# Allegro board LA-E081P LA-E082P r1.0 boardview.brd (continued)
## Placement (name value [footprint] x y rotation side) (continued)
PR943  0_0603_5%  [R0603_0OHM]  14.27 21.56 90 top
PR944  442K_0402_1%  [R_0402]  12.29 16.01 0 bottom
PR945  100K_0402_5%  [R_0402]  13.21 17.77 180 bottom
PR946  0_0402_5%  [R0402_0OHM]  28.7 29.88 180 top
PR947  0_0402_5%  [R0402_0OHM]  18.17 8.27 0 top
PR948  16.5K_0402_1%  [R_0402]  20.07 12.39 270 top
PR949  0_0402_5%  [R0402_0OHM]  18.24 12.39 270 top
PR950  0_0402_5%  [R_0402]  28.71 25.55 180 top
PR951  0_0402_5%  [R0402_0OHM]  14.61 11.45 90 top
PR953  100K_0402_1%  [R_0402]  25.85 29.05 180 top
PR960  0_0402_5%  [R0402_0OHM]  12.32 18.57 270 top
PR1201  240K_0402_1%  [R_0402]  67.2 111.31 270 top
PR1202  300K_0402_1%  [R_0402]  4.2 39.23 90 top
PR1203  1.8M_0402_1%  [R_0402]  68.1 109.14 180 top
PR1205  499K_0402_1%  [R_0402]  7.75 51.58 270 top
PR1206  1K_0402_1%  [R_0402]  64.54 109.59 0 bottom
PR1207  499K_0402_1%  [R_0402]  9.39 41.72 0 top
PR1208  102K_0402_1%  [R_0402]  66.42 112.18 270 bottom
PR1209  100K_0402_5%  [R_0402]  3.22 40.12 270 top
PR1210  1M_0402_5%  [R_0402]  12.74 37.69 0 top
PR1211  0_0402_5%  [R0402_0OHM]  18.03 37.73 0 top
PR1212  49.9K_0402_1%  [R_0402]  3.64 49.36 180 top
PR1213  49.9K_0402_1%  [R_0402]  10.29 40.66 270 top
PR1214  100K_0402_5%  [R_0402]  18.3 31.83 180 top
PR1215  0_0402_5%  [R0402_0OHM]  23.25 33.93 90 top
PR1216  0_0402_5%  [R0402_0OHM]  17.15 33.63 180 top
PR1217  84.5K_0402_1%  [R_0402]  67.32 112.16 0 bottom
PR1218  0_0402_5%  [R0402_0OHM]  16.46 31.78 90 top
PR1219  23.2K_0402_1%  [R_0402]  68.07 111.27 0 top
PR1220  0_0402_5%  [R0402_0OHM]  15.24 37.54 0 top
PR1221  0_0402_5%  [R0402_0OHM]  21.34 34.44 0 top
PR1222  100K_0402_5%  [R_0402]  16.13 38.5 180 top
PR1223  0_0402_5%  [R0402_0OHM]  14.36 31.11 180 top
PR1224  100K_0402_5%  [R_0402]  22.23 35.32 90 top
PR1225  0_0402_5%  [R0402_0OHM]  22.1 30.88 180 top
PR1226  100K_0402_5%  [R_0402]  23.25 32.02 90 top
PR1227  100K_0402_5%  [R_0402]  16.64 85.11 270 top
PR1228  499K_0402_1%  [R_0402]  13.98 51.45 0 top
PR1229  49.9K_0402_1%  [R_0402]  15.93 52.29 90 top
PR1230  100K_0402_5%  [R_0402]  25.28 31.25 90 top
PR1231  100K_0402_5%  [R_0402]  31.78 33.76 270 top
PR1232  100K_0402_5%  [R_0402]  28.84 37.56 0 top
PR1233  100K_0402_5%  [R_0402]  28 31.26 0 top
PR1234  100K_0402_5%  [R_0402]  25.48 36.89 90 top
PR1235  100K_0402_5%  [R_0402]  25.41 34.18 270 top
PR1236  100K_0402_5%  [R_0402]  18.7 55.83 180 top
PR1237  100K_0402_1%  [R_0402]  69.24 103.04 90 bottom
PR1238  0_0402_5%  [R0402_0OHM]  68.65 105.44 180 top
PR1239  150K_0402_1%  [R_0402]  72.76 105.66 180 bottom
PR1240  100K_0402_1%  [R_0402]  67.54 103 90 top
PR1241  0_0402_5%  [R0402_0OHM]  32.28 36.09 180 top
PR1242  0_0402_5%  [R0402_0OHM]  26.22 31.26 0 top
PR1243  0_0402_5%  [R0402_0OHM]  66.61 103.91 270 top
PR1244  0_0402_5%  [R0402_0OHM]  65.46 108.65 180 bottom
PR1245  0_0402_5%  [R0402_0OHM]  30.87 31.32 180 top
PR1246  100K_0402_1%  [R_0402]  71.84 106.63 0 bottom
PR1247  100K_0402_1%  [R_0402]  68.36 103.95 270 bottom
PR1248  0_0402_5%  [R_0402]  69.92 110.26 0 top
PR1249  10K_0402_5%  [R_0402]  69.98 112.18 180 top
PR1250  0_0402_5%  [R0402_0OHM]  69.94 111.21 0 top
PR1251  300K_0402_1%  [R_0402]  3.17 55.01 0 top
PR1252  100K_0402_5%  [R_0402]  10.96 37.68 0 top
PR1253  100K_0402_5%  [R_0402]  11.05 33.55 0 top
PR1254  0_0402_5%  [R_0402]  18.04 38.63 0 top
PR1255  150K_0402_1%  [R_0402]  13.98 49.68 0 top
PR1257  0_0402_5%  [R0402_0OHM]  24.52 33.27 90 top
PR1258  0_0402_5%  [R_0402]  32.28 35.2 180 top
PR1259  100K_0402_5%  [R_0402]  26.55 38.25 0 top
PR1260  0_0402_5%  [R_0402]  24.52 35.98 270 top
PR1261  0_0402_5%  [R_0402]  25.41 35.07 90 top
PRP1  100_0804_8P4R_5%  [RP_0804_8P4R]  19.45 5.54 90 top
PT1  PAD~D  [TPC12]  71.75 111.45 0 top
PU1  MC74VHC1G08DFT2G_SC70-5  [TC7SH08FU_SSOP5]  65.25 96.09 270 bottom
PU2  AP2204RA-3.3TRG1_SOT89-3  [AP2204RA-3P3TRG1_SOT89-3]  72.27 101.21 90 bottom
PU100  -  [SY8288BRAC_QFN20_3X3]  156.99 111.26 180 top
PU102  -  [SY8288CRAC_QFN20_3X3]  166.14 113.72 0 bottom
PU200  -  [SY8210AQVC_QFN19_4X3]  44.21 49.79 270 bottom
PU301  SY8286RAC_QFN20_3X3  [SY8288RAC_QFN20_3X3]  179.56 93.48 0 bottom
PU401  TPS62134CRGT_QFN16_3X3  [SY8057QDC_QFN16_3X3]  140.48 108.18 90 top
PU402  TPS62134DRGT_QFN16_3X3  [SY8057QDC_QFN16_3X3]  130.08 110.54 90 top
PU501  -  [RT8097ALGE_SOT23-6]  122.1 105.89 0 top
PU503  -  [AP7361C-FGE-7_U-DFN3030-8_3X3]  193.24 4.81 270 top
PU602  ISL95857AHRTZTS27_TQFN40_5X5~D  [ISL62883CHRTZ-T_TQFN40_5X5-S]  70.56 52.66 180 top
PU610  CSD97396Q4M_VSON8_3P5X4P5  [CSD97374CQ4M_SON8_3P5X4P5]  61.89 71.83 270 bottom
PU612  CSD97396Q4M_VSON8_3P5X4P5  [CSD97374CQ4M_SON8_3P5X4P5]  61.86 65.89 270 bottom
PU614  ISL95808HRZ-TS2778_DFN8_2X2~D  [ISL95808HRZ-TS2378_DFN8_2X2-S]  67.09 78.76 0 bottom
PU901  ISL88738HRTZ REV.B-T TQFN 32P PWM  [ISL88738HRTZ-T_TQFN32_4X4]  20.5 15.56 180 top
PU903  MC74VHC1G08DFT2G_SC70-5  [TC7SH08FU_SSOP5]  29.87 27.6 90 top
PU1200  MC74VHC1G08DFT2G_SC70-5  [TC7SH08FU_SSOP5]  18.79 36.64 180 top
PU1201  -  [LM393DGKR_VSSOP8]  66.92 109.73 270 bottom
QC2  -  [DMN65D8LDW-7_SOT363-6]  151.96 65.6 90 top
QE2  -  [DMN65D8LDW-7_SOT363-6]  298.22 61.93 180 top
QE3  LMBT3904WT1G SC70-3  [MMBT3904WT1G_SC70-3]  122.98 58.09 90 top
QE4  LMBT3904WT1G SC70-3  [MMBT3904WT1G_SC70-3]  284.1 72.92 90 top
QE5  LMBT3904WT1G SC70-3  [MMBT3904WT1G_SC70-3]  239.15 8.97 180 bottom
QE6  LMBT3904WT1G SC70-3  [MMBT3904WT1G_SC70-3]  78.75 48.66 180 top
QE7  LMBT3904WT1G SC70-3  [MMBT3904WT1G_SC70-3]  113.04 8.27 180 bottom
QE11  -  [L2N7002WT1G_SC-70-3]  280.04 70.44 180 top
QE12  -  [L2N7002WT1G_SC-70-3]  287.15 72.98 180 top
QE13  -  [DMN65D8LDW-7_SOT363-6]  293.39 90.63 180 top
QL1  -  [DMN65D8LDW-7_SOT363-6]  283.15 97.67 90 top
QL2  -  [DMN65D8LDW-7_SOT363-6]  278.2 98.97 270 top
QN1  -  [DMN65D8LDW-7_SOT363-6]  281.18 38.5 90 top
QN4  DMN65D8LDW-7_SOT363-6  [DMN66D0LDW-7_SOT363-6]  208.73 35.72 270 top
QN5  DMN65D8LDW-7_SOT363-6  [DMN66D0LDW-7_SOT363-6]  223.84 34.17 90 top
QR1  -  [L2N7002WT1G_SC-70-3]  32.96 52.98 180 top
QT1  -  [DMN66D0LDW-7_SOT363-6]  37.39 81.05 0 top
QV1  -  [AO6405_TSOP6]  109.79 80.95 180 bottom
QV2  -  [L2N7002WT1G_SC-70-3]  102.17 81.99 90 bottom
QV3  -  [DMN65D8LDW-7_SOT363-6]  115 110.97 270 bottom
QV4  -  [L2N7002WT1G_SC-70-3]  112.15 102.33 0 top
QV5  -  [L2N7002WT1G_SC-70-3]  116.14 108.32 180 top
QV7  -  [L2N7002WT1G_SC-70-3]  120.91 83.84 180 bottom
QV8  -  [LP2301ALT1G_SOT23-3]  124.72 88.66 90 bottom
QZ1  -  [LP2301ALT1G_SOT23-3]  112.91 83.8 0 bottom
QZ2  -  [DMN65D8LDW-7_SOT363-6]  267.33 64.85 0 top
QZ3  DDTA114EUA-7-F_SOT323-3  [DDTA144VCA-7-F_SOT23-3]  269.58 73.68 180 top
QZ7  -  [DMN65D8LDW-7_SOT363-6]  315.71 97.49 0 bottom
QZ8  -  [L2N7002WT1G_SC-70-3]  292.49 67.02 90 top
QZ9  -  [LP2301ALT1G_SOT23-3]  173.96 43.39 90 top
R274  0_0603_5%  [R0603_0OHM]  20.96 44.79 90 top
RA3  0_0603_5%  [R0603_0OHM]  302.65 42.5 90 top
RA5  2.2K_0402_5%  [R_0402]  310.22 38.12 180 bottom
RA6  2.2K_0402_5%  [R_0402]  310.22 35.58 180 bottom
RA7  16.2_0402_1%  [R_0402]  307.09 38.32 270 top
RA8  16.2_0402_1%  [R_0402]  307.09 35.63 90 top
RA9  33_0402_5%  [R_0402]  290.82 36.15 0 top
RA12  1K_0402_5%  [R_0402]  300.47 28.09 0 top
RA13  1K_0402_5%  [R_0402]  295.79 29.05 270 top
RA14  22_0402_5%  [R_0402]  292.6 37.99 0 top
RA17  33_0402_5%  [R_0402]  293.51 37.1 180 top
RA18  10K_0402_5%  [R_0402]  296.02 40.92 180 top
RA35  0_0402_5%  [R0402_0OHM]  308.42 42.87 90 top
RA36  0_0402_5%  [R0402_0OHM]  307.54 42.87 90 top
RA37  0_0402_5%  [R0402_0OHM]  294.47 29.04 180 top
RA44  100K_0402_5%  [R_0402]  306.89 32.15 0 top
RA45  10K_0402_5%  [R_0402]  297.69 29.05 270 top
RA48  0_0402_5%  [R0402_0OHM]  296.11 44.04 270 top
RA50  0_0402_5%  [R_0402]  296.87 41.34 90 top
RA51  10K_0402_5%  [R_0402]  298.71 29.05 270 top
RA52  100K_0402_5%  [R_0402]  292.36 38.88 0 top
RA53  0_0402_5%  [R_0402]  303.79 29.11 270 top
RA54  0_0402_5%  [R0402_0OHM]  302.9 29.11 270 top
RA57  4.7K_0402_5%  [R_0402]  305.37 36.52 45 top
RA58  4.7K_0402_5%  [R_0402]  305.37 35.25 45 top
RA59  100K_0402_1%  [R_0402]  293.62 31.9 0 top
RA60  200K_0402_1%  [R_0402]  294.45 30.83 270 top
RA61  100K_0402_1%  [R_0402]  296.22 30.8 0 top
RC1  100K_0402_5%  [R_0402]  132.29 62.5 180 top
RC2  24.9_0402_1%  [R_0402]  108.09 67.58 180 top
RC3  100_0402_1%  [R_0402]  128.91 78.5 0 top
RC4  200_0402_1%  [R_0402]  145.6 52.85 0 bottom
RC5  121_0402_1%  [R_0402]  130.94 42.83 270 top
RC6  80.6_0402_1%  [R_0402]  128.91 42.83 270 top
RC7  100_0402_1%  [R_0402]  129.93 42.83 270 top
RC10  1K_0402_1%  [R_0402]  166.29 49.81 270 top
RC11  1K_0402_1%  [R_0402]  161.46 49.81 270 top
RC12  1K_0402_5%  [R_0402]  148.67 65.1 180 top
RC13  10K_0402_5%  [R_0402]  133.74 37.74 270 top
RC14  1K_0402_5%  [R_0402]  153.34 67.01 0 top
RC15  1K_0402_5%  [R_0402]  145.67 62.5 0 bottom
RC16  15_0402_5%  [R_0402]  138.82 41.92 90 top
RC17  1K_0402_5%  [R_0402]  145.67 64.66 0 bottom
RC19  499_0402_1%  [R_0402]  150.12 59.33 0 bottom
RC20  499_0402_1%  [R_0402]  149.23 61.49 180 bottom
RC21  8.2K_0402_1%  [R_0402]  137.55 39.77 270 top
RC22  22_0402_5%  [R_0402]  142.5 36.72 270 top
RC23  2.2K_0402_5%  [R_0402]  144.45 63.96 0 top
RC25  4.7K_0402_5%  [R_0402]  145.67 61.36 0 bottom
RC27  8.2K_0402_5%  [R_0402]  138.44 39.77 270 top
RC28  33_0402_5%  [R_0402]  151.34 54.69 180 bottom
RC29  33_0402_5%  [R_0402]  152.02 64.41 270 bottom
RC30  1K_0402_5%  [R_0402]  162.44 58.17 90 bottom
RC31  1K_0402_5%  [R_0402]  156.6 61.12 270 top
RC32  0_0402_5%  [R_0402]  167.3 49.81 270 bottom
RC33  0_0402_5%  [R0402_0OHM]  166.29 49.81 270 bottom
RC34  0_0402_5%  [R0402_0OHM]  165.33 49.8 270 bottom
RC35  0_0402_5%  [R0402_0OHM]  163.81 49.8 270 bottom
RC36  0_0402_5%  [R0402_0OHM]  162.48 49.81 270 bottom
RC37  0_0402_5%  [R0402_0OHM]  162.69 66.36 90 bottom
RC38  0_0402_5%  [R0402_0OHM]  161.46 49.81 270 bottom
RC39  33_0402_5%  [R_0402]  162.69 63.82 90 bottom
RC40  0_0402_5%  [R0402_0OHM]  160.44 49.81 270 bottom
RC41  0_0402_5%  [R0402_0OHM]  159.43 48.9 90 bottom
RC42  0_0402_5%  [R_0402]  160.66 61.37 270 bottom
RC43  33_0402_5%  [R_0402]  162.44 57.12 270 bottom
RC44  113_0402_1%  [R_0402]  130.49 58.27 180 top
RC45  100_0402_1%  [R_0402]  132.33 67.87 0 top
RC46  1M_0402_1%  [R_0402]  117.39 78.42 180 bottom
RC47  10K_0402_5%  [R_0402]  146.56 36.72 270 top
RC48  1K_0402_5%  [R_0402]  133.74 39.78 270 top
RC50  10K_0402_5%  [R_0402]  144.79 36.72 270 top
RC51  10K_0402_5%  [R_0402]  145.67 33.68 270 top
RC52  2.7K_0402_1%  [R_0402]  124.66 61.47 90 top
RC54  10M_0402_5%  [R_0402]  151.52 42.18 0 bottom
RC56  20K_0402_5%  [R_0402]  135.77 39.78 270 top
RC57  20K_0402_5%  [R_0402]  154.63 52.36 270 bottom
RC59  10K_0402_5%  [R_0402]  149.36 36.73 270 top
RC60  0_0402_5%  [R_0402]  157.55 50.45 270 bottom
RC62  0_0402_5%  [R0402_0OHM]  161.02 52.05 90 bottom
RC65  100K_0402_5%  [R_0402]  155.78 50.37 180 bottom
RC67  1K_0402_5%  [R_0402]  132.21 36.34 270 top
RC68  10K_0402_5%  [R_0402]  135.13 30.76 270 top
RC69  1M_0402_5%  [R_0402]  135.77 36.98 90 top
RC71  1K_0402_5%  [R_0402]  97.67 79 90 bottom
RC72  8.2K_0402_5%  [R_0402]  150.75 33.67 270 top
RC73  10K_0402_5%  [R_0402]  151.77 33.67 270 top
RC74  10K_0402_5%  [R_0402]  143.77 36.72 270 top
RC75  10K_0402_5%  [R_0402]  132.85 39.77 270 top
RC77  1K_0402_5%  [R_0402]  90.24 81.16 270 bottom
RC78  60.4_0402_1%  [R_0402]  97.57 77.12 270 bottom
RC79  49.9_0402_1%  [R_0402]  101.61 75.46 90 bottom
RC80  1K_0402_5%  [R_0402]  100.72 79 90 bottom
RC81  51_0402_5%  [R_0402]  103.76 79 90 bottom
RC82  100_0402_5%  [R_0402]  105.8 79 90 bottom
RC83  1K_0402_5%  [R_0402]  93.66 80.24 90 bottom
RC84  499_0402_1%  [R_0402]  96.65 79.91 270 bottom
RC86  51_0402_5%  [R_0402]  104.91 75.46 90 bottom
RC87  1K_0402_5%  [R_0402]  101.73 79 90 bottom
RC88  49.9_0402_1%  [R_0402]  132.85 42.83 270 top
RC89  49.9_0402_1%  [R_0402]  131.96 42.83 270 top
RC90  49.9_0402_1%  [R_0402]  90.86 67.42 180 bottom
RC91  49.9_0402_1%  [R_0402]  90.86 66.41 180 bottom
RC92  33_0402_5%  [R_0402]  128.91 35.44 90 top
RC93  33_0402_5%  [R_0402]  127.02 36.4 180 top
RC94  33_0402_5%  [R_0402]  128.94 38.4 90 top
RC95  33_0402_5%  [R_0402]  128.02 34.61 90 top
RC96  200_0402_1%  [R_0402]  150.12 59.45 90 top
RC109  1K_0402_5%  [R_0402]  88.91 80.38 90 bottom
RC110  10K_0402_1%  [R_0402]  95.51 75.46 180 bottom
RC112  10K_0402_1%  [R_0402]  92.27 80.24 90 bottom
RC113  10K_0402_1%  [R_0402]  95.51 76.47 180 bottom
RC114  49.9_0402_1%  [R_0402]  103.21 67.84 180 top
RC115  1.5K_0402_5%  [R_0402]  130.82 86.25 180 top
RC120  100K_0402_5%  [R_0402]  98.68 79 90 bottom
RC121  0_0402_5%  [R_0402]  77.09 38.36 90 top
RC122  0_0402_5%  [R_0402]  76.08 38.36 90 top
RC123  1K_0402_5%  [R_0402]  67.95 39.27 270 top
RC124  1K_0402_5%  [R_0402]  68.97 39.27 270 top
RC126  1K_0402_5%  [R_0402]  73.54 38.36 90 top
RC128  0_0402_5%  [R_0402]  61.35 41.56 270 top
RC129  0_0402_5%  [R_0402]  62.36 41.56 270 top
RC130  51_0402_5%  [R_0402]  102.75 79 90 bottom
RC131  51_0402_5%  [R_0402]  51.19 29.3 270 top
RC132  150_0402_5%  [R_0402]  63.38 38.36 90 top
RC133  1.5K_0402_5%  [R_0402]  60.33 41.56 270 top
RC134  51_0402_5%  [R_0402]  51.69 35.82 90 top
RC135  100_0402_5%  [R_0402]  53.73 35.82 90 top
RC136  51_0402_5%  [R_0402]  54.23 29.3 270 top
RC137  3K_0402_5%  [R_0402]  62.87 27.59 270 top
RC138  51_0402_5%  [R_0402]  75.06 38.36 90 top
RC139  51_0402_5%  [R_0402]  61.35 38.36 90 top
RC140  100_0402_1%  [R_0402]  113.29 76.74 90 bottom
RC141  100_0402_1%  [R_0402]  114.16 76.74 90 bottom
RC143  0_0603_5%  [R0603_0OHM]  123.69 65.16 180 top
RC152  56_0402_1%  [R_0402]  99.7 76.71 90 bottom
RC153  220_0402_5%  [R_0402]  98.81 75.46 0 bottom
RC157  100_0402_1%  [R_0402]  98.68 76.71 90 bottom
RC161  100_0402_1%  [R_0402]  90.88 64.47 180 bottom
RC163  100_0402_1%  [R_0402]  90.86 65.44 180 bottom
RC165  100_0402_1%  [R_0402]  122.51 53.8 180 top
RC166  100_0402_1%  [R_0402]  121.16 80.39 90 top
RC167  100_0402_1%  [R_0402]  123.58 53.85 90 top
RC168  100_0402_1%  [R_0402]  122.43 81.3 270 top
RC169  0_0603_5%  [R0603_0OHM]  148.53 72.15 180 top
RC170  0_0402_5%  [R0402_0OHM]  125.46 81.16 270 top
RC171  0_0402_5%  [R0402_0OHM]  136.53 85.57 270 top
RC173  0_0402_5%  [R0402_0OHM]  126.37 80.41 180 bottom
RC175  2.2K_0402_5%  [R_0402]  140.09 88.97 90 top
RC176  2.2K_0402_5%  [R_0402]  121.35 83.91 90 top
RC177  2.2K_0402_5%  [R_0402]  120.34 83.91 90 top
RC178  2.2K_0402_5%  [R_0402]  139.07 88.97 90 top
RC183  8.2K_0402_5%  [R_0402]  148.34 36.72 270 top
RC184  8.2K_0402_5%  [R_0402]  149.74 39.85 270 top
RC186  4.7K_0402_5%  [R_0402]  148.72 33.68 270 top
RC187  4.7K_0402_5%  [R_0402]  130.94 39.77 270 top
RC189  10K_0402_5%  [R_0402]  147.71 33.68 270 top
RC190  10K_0402_5%  [R_0402]  141.86 38.89 270 top
RC211  0_0402_5%  [R_0402]  154.69 56.03 270 top
RC212  0_0402_5%  [R0402_0OHM]  155.58 56.03 270 top
RC214  0_0402_5%  [R0402_0OHM]  137.8 41.91 90 top
RC215  0_0402_5%  [R_0402]  131.83 38.88 90 top
RC216  0_0603_1%  [R0603_0OHM]  65.92 26.18 90 top
RC217  0_0402_5%  [R_0402]  63.38 41.56 270 top
RC218  150_0402_5%  [R_0402]  64.39 41.56 270 top
RC219  10K_0402_5%  [R_0402]  65.41 41.56 270 top
RC220  100K_0402_1%  [R_0402]  131.07 36.35 270 top
RC221  0_0402_5%  [R0402_0OHM]  278.77 92.02 90 bottom
RC222  1K_0402_5%  [R_0402]  279.79 92.02 90 bottom
RC223  1K_0402_5%  [R_0402]  129.82 38.4 90 top
RC224  1K_0402_5%  [R_0402]  148.16 88.47 180 bottom
RC225  8.2K_0402_5%  [R_0402]  151.39 90.81 90 bottom
RC227  8.2K_0402_5%  [R_0402]  151.39 89.44 270 bottom
RC228  0_0402_5%  [R0402_0OHM]  52.2 29.3 270 top
RC229  0_0402_5%  [R0402_0OHM]  52.71 35.82 90 top
RC230  0_0402_5%  [R0402_0OHM]  104.78 79.91 270 bottom
RC231  0_0402_5%  [R0402_0OHM]  111.89 54.12 180 top
RC234  0_0402_5%  [R_0402]  151.21 56.85 180 bottom
RC235  0_0402_5%  [R0402_0OHM]  151.21 56.85 180 top
RC237  10K_0402_5%  [R_0402]  150.35 54.88 0 top
RC239  0_0402_5%  [R_0402]  71.25 39.27 270 top
RC240  0_0402_5%  [R_0402]  70.24 39.27 270 top
RC241  1.5K_0402_5%  [R_0402]  64.9 38.36 90 top
RC243  10K_0402_5%  [R_0402]  133.36 31.26 270 top
RC244  0_0402_5%  [R0402_0OHM]  160.13 52.05 90 bottom
RC267  10K_0402_5%  [R_0402]  147.71 39.85 270 top
RC268  10K_0402_5%  [R_0402]  148.72 39.85 270 top
RC272  10K_0402_5%  [R_0402]  137.93 81.17 180 bottom
RC278  10K_0402_5%  [R_0402]  151.64 39.77 270 top
RC279  10K_0402_5%  [R_0402]  144.53 58.57 0 top
RC282  100K_0402_5%  [R_0402]  152.79 54.88 0 top
RC283  10K_0402_5%  [R_0402]  145.6 57.86 0 bottom
RC287  100K_0402_5%  [R_0402]  145.6 58.88 0 bottom
RC288  10K_0402_5%  [R_0402]  147.2 75.84 0 top
RC290  0_0402_5%  [R0402_0OHM]  150.2 88.47 180 bottom
RC291  10K_0402_5%  [R_0402]  146.31 89.79 90 bottom
RC292  10K_0402_5%  [R_0402]  133.61 86.51 270 top
RC295  33_0402_5%  [R_0402]  117.44 79.32 0 bottom
RC296  0_0402_5%  [R0402_0OHM]  150.63 42.18 90 bottom
RC297  0_0402_5%  [R_0402]  112.38 76.74 90 bottom
RC298  0_0402_5%  [R_0402]  111.49 76.74 90 bottom
RC299  0_0603_5%  [R0603_0OHM]  133.74 82.06 270 bottom
RC300  0_0402_5%  [R0402_0OHM]  138.51 85.62 180 top
RC301  0_0402_5%  [R0402_0OHM]  146.49 66.31 180 bottom
RC302  0_0402_5%  [R0402_0OHM]  132.59 86.25 180 top
RC303  0_0402_5%  [R0402_0OHM]  128.26 80.9 270 top
RC304  0_0402_5%  [R0402_0OHM]  145.42 59.58 180 top
RC305  0_0402_5%  [R0402_0OHM]  130.87 56.36 180 top
RC306  0_0402_5%  [R0402_0OHM]  151.25 57.73 180 top
RC307  0_0402_5%  [R0402_0OHM]  145.42 57.55 180 top
RC308  0_0402_5%  [R0402_0OHM]  145.42 60.47 180 top
RC309  0_0603_5%  [R0603_0OHM]  120.02 79.9 90 top
RC310  0_0603_5%  [R0603_0OHM]  148.6 73.42 180 top
RC311  10K_0402_5%  [R_0402]  133.99 42.83 270 top
RC313  0_0402_5%  [R_0402]  145.29 69.11 180 top
RC316  1K_0402_5%  [R_0402]  155.58 61.12 270 top
RC317  150K_0402_5%  [R_0402]  148.98 57.55 180 bottom
RC318  2.2K_0402_5%  [R_0402]  148.16 67.01 180 top
RC319  2.2K_0402_5%  [R_0402]  153.34 65.99 0 top
RC323  10K_0402_5%  [R_0402]  143.64 33.68 270 top
RC324  59_0402_1%  [R_0402]  113.52 67.24 270 top
RC325  0_0402_5%  [R0402_0OHM]  156.66 50.45 270 bottom
RC328  0_0402_5%  [R0402_0OHM]  102.49 78 180 bottom
RC330  49.9K_0402_1%  [R_0402]  145.6 54.82 0 bottom
RC331  49.9K_0402_1%  [R_0402]  145.6 55.83 0 bottom
RC337  0_0402_5%  [R0402_0OHM]  151.77 36.8 270 top
RC338  1K_0402_5%  [R_0402]  150.75 39.85 270 top
RC344  10K_0402_5%  [R_0402]  136.15 30.76 270 top
RC345  100K_0402_5%  [R_0402]  144.4 68.22 0 top
RC346  10K_0402_5%  [R_0402]  151.52 75.33 0 bottom
RC347  499_0402_1%  [R_0402]  150.12 60.22 0 bottom
RC348  499_0402_1%  [R_0402]  150.12 61.49 0 bottom
RC349  100_0402_1%  [R_0402]  140.09 39.77 270 top
RC362  1K_0402_5%  [R_0402]  147.96 54.76 0 top
RC363  1K_0402_5%  [R_0402]  147.96 55.64 0 top
RC366  15_0402_5%  [R_0402]  138.69 36.72 270 top
RC367  15_0402_5%  [R_0402]  139.58 36.72 270 top
RC368  15_0402_5%  [R_0402]  136.66 39.77 270 top
RC369  15_0402_5%  [R_0402]  140.59 36.72 270 top
RC370  10K_0402_5%  [R_0402]  153.42 39.77 270 top
RC371  10K_0402_5%  [R_0402]  145.57 67.33 0 bottom
RC372  10K_0402_5%  [R_0402]  148.09 67.84 0 bottom
RC373  0_0402_5%  [R0402_0OHM]  146.69 33.68 270 top
RC374  0_0402_5%  [R0402_0OHM]  147.45 36.72 270 top
RC375  0_0402_5%  [R0402_0OHM]  145.67 36.72 270 top
RC376  0_0402_5%  [R0402_0OHM]  150.37 36.73 270 top
RC377  0_0402_5%  [R0402_0OHM]  144.66 33.68 270 top
RC378  0_0402_5%  [R0402_0OHM]  140.98 38.88 270 top
RC387  10K_0402_5%  [R_0402]  149.74 33.68 270 top
RC400  10K_0402_5%  [R_0402]  145.57 68.22 0 bottom
RC401  10K_0402_5%  [R_0402]  148.09 68.73 0 bottom
RC402  49.9K_0402_1%  [R_0402]  145.6 53.8 0 bottom
RC403  49.9K_0402_1%  [R_0402]  145.6 56.85 0 bottom
RC404  10K_0402_5%  [R_0402]  144.4 67.33 0 top
RC405  100K_0402_5%  [R_0402]  145.67 59.84 0 bottom
RC407  33_0402_5%  [R_0402]  156.66 61.37 270 bottom
RC408  33_0402_5%  [R_0402]  157.61 61.37 270 bottom
RC409  33_0402_5%  [R_0402]  158.63 61.37 270 bottom
RC410  33_0402_5%  [R_0402]  159.64 61.37 270 bottom
RC411  10K_0402_5%  [R_0402]  125.16 36.42 270 top
RC413  10K_0402_5%  [R_0402]  141.1 88.97 90 top
RC414  10K_0402_5%  [R_0402]  140.85 42.83 270 top
RC417  33_0402_5%  [R_0402]  115.66 79.33 0 bottom
RD4  0_0402_5%  [R_0402]  103.64 3.05 90 top
RD5  0_0402_5%  [R0402_0OHM]  102.62 3.97 270 top
RD6  0_0402_5%  [R_0402]  104.65 3.05 90 top
RD7  0_0402_5%  [R0402_0OHM]  105.67 3.97 270 top
RD8  0_0402_5%  [R_0402]  88.52 2.29 90 top
RD9  0_0402_5%  [R0402_0OHM]  88.52 4.32 90 top
RD10  0_0603_5%  [R0603_0OHM]  106.13 7.56 180 top
RD11  470_0402_1%  [R_0402]  64.9 4.22 270 top
RD12  0_0402_5%  [R0402_0OHM]  65.92 4.22 270 top
RD14  1K_0402_5%  [R_0402]  73.03 4.32 90 top
RD15  1K_0402_1%  [R_0402]  86.7 5.29 180 top
RD16  1K_0402_1%  [R_0402]  85.78 4.27 0 top
RD17  2_0402_1%  [R_0402]  83.95 5.24 270 top
RD18  24.9_0402_1%  [R_0402]  85.78 3.25 0 top
RD19  100K_0402_5%  [R_0402]  65.66 18.7 270 top
RD20  0_0402_5%  [R_0402]  186.06 2.29 90 top
RD21  0_0402_5%  [R0402_0OHM]  187.08 3.2 270 top
RD22  0_0402_5%  [R0402_0OHM]  189.11 2.29 90 top
RD23  0_0402_5%  [R_0402]  188.09 3.2 270 top
RD24  0_0402_5%  [R_0402]  169.71 3.5 180 top
RD25  0_0402_5%  [R0402_0OHM]  168.8 2.49 0 top
RD26  0_0603_5%  [R0603_0OHM]  187.84 13.6 270 top
RD27  1K_0402_5%  [R_0402]  141.46 2.49 180 top
RD28  1K_0402_1%  [R_0402]  171.48 5.31 270 top
RD29  1K_0402_1%  [R_0402]  170.46 4.4 90 top
RD30  2_0402_1%  [R_0402]  171.2 3.2 270 top
RD31  24.9_0402_1%  [R_0402]  173.23 3.2 270 top
RE5  10K_0402_5%  [R_0402]  299.22 83.93 90 top
RE6  10K_0402_5%  [R_0402]  41.52 81.04 0 bottom
RE8  100K_0402_5%  [R_0402]  304.81 83.84 90 top
RE10  100K_0402_5%  [R_0402]  307.4 70.08 0 top
RE11  100K_0402_5%  [R_0402]  296.49 69.38 270 top
RE12  100K_0402_5%  [R_0402]  308.11 65.93 270 top
RE13  10K_0402_5%  [R_0402]  41.46 74.95 0 bottom
RE14  10K_0402_5%  [R_0402]  42.37 75.96 180 bottom
RE15  10K_0402_5%  [R_0402]  41.46 78 0 bottom
RE16  10K_0402_5%  [R_0402]  42.37 76.98 180 bottom
RE17  10K_0402_5%  [R_0402]  41.46 79.01 0 bottom
RE18  10K_0402_5%  [R_0402]  42.44 80.03 180 bottom
RE20  100K_0402_5%  [R_0402]  298.28 69.47 270 top
RE21  10K_0402_5%  [R_0402]  299.09 64.46 90 top
RE25  100K_0402_5%  [R_0402]  307.46 85.04 0 top
RE26  10_0402_5%  [R_0402]  308.52 86.86 270 top
RE30  0_0402_5%  [R0402_0OHM]  274.15 78.44 180 bottom
RE31  100K_0402_5%  [R_0402]  286.9 69.92 90 top
RE32  0_0402_5%  [R0402_0OHM]  290.05 77.95 180 top
RE33  1K_0402_5%  [R_0402]  285.88 70.83 270 top
RE34  0_0402_5%  [R0402_0OHM]  284.87 79.58 180 top
RE35  10K_0402_5%  [R_0402]  306.58 84.14 90 top
RE37  2.2K_0402_5%  [R_0402]  307.36 71.85 0 top
RE38  10K_0402_5%  [R_0402]  305.69 84.14 90 top
RE43  2.2K_0402_5%  [R_0402]  307.4 70.97 0 top
RE48  10K_0402_5%  [R_0402]  270.39 41.5 270 bottom
RE51  10K_0402_5%  [R_0402]  266.96 41.29 40 top
RE55  100K_0402_5%  [R_0402]  293.79 69.67 270 top
RE56  10K_0402_5%  [R_0402]  302.83 68.78 270 top
RE57  1K_0402_5%  [R_0402]  295.58 69.41 270 top
RE58  100K_0402_5%  [R_0402]  294.69 69.67 270 top
RE59  0_0402_5%  [R0402_0OHM]  305.65 87.43 270 top
RE60  43_0402_5%  [R_0402]  302.71 83.8 90 top
RE63  100K_0402_5%  [R_0402]  300.87 87.14 90 top
RE64  300_0402_5%  [R_0402]  304.82 68 270 top
RE65  100_0402_1%  [R_0402]  300.17 86 180 top
RE67  10K_0402_5%  [R_0402]  297.06 62.93 90 top
RE68  100K_0402_5%  [R_0402]  297.64 58.95 180 top
RE69  8.2K_0402_5%  [R_0402]  284.41 74.19 0 top
RE70  2.2K_0402_5%  [R_0402]  279.58 73.68 0 top
RE71  49.9_0402_1%  [R_0402]  273.23 79.46 0 bottom
RE72  10K_0402_5%  [R_0402]  273.23 77.42 0 bottom
RE73  10K_0402_5%  [R_0402]  273.23 73.36 0 bottom
RE74  10K_0402_5%  [R_0402]  273.23 72.34 0 bottom
RE75  100K_0402_5%  [R_0402]  273.23 75.39 0 bottom
RE77  1.69K_0402_1%  [R_0402]  293.32 82.57 180 top
RE79  4.3K_0402_5%  [R_0402]  303.79 83.84 90 top
RE83  100K_0402_5%  [R_0402]  302.65 87.14 90 top
RE84  100K_0402_5%  [R_0402]  300.74 92.78 90 top
RE85  100K_0402_5%  [R_0402]  299.73 92.78 90 top
RE86  10K_0402_5%  [R_0402]  274.15 76.41 180 bottom
RE90  0_0402_5%  [R0402_0OHM]  280.5 74.69 180 top
RE91  100K_0402_5%  [R_0402]  301.76 87.14 90 top
RE92  100K_0402_5%  [R_0402]  289.36 68.6 0 top
RE93  100K_0201_5%  [R_0201]  287.7 75.84 180 top
RE94  75_0402_5%  [R_0402]  287.2 71.77 0 top
RE95  100K_0402_5%  [R_0402]  313.62 78.25 0 top
RE98  4.7K_0402_5%  [R_0402]  314.33 67.07 180 top
RE274  0_0402_5%  [R_0402]  308.44 68.31 180 top
RE275  0_0402_5%  [R0402_0OHM]  307.51 67.42 0 top
RE280  0_0402_5%  [R_0402]  305.64 96.03 180 top
RE288  100_0402_5%  [R_0402]  301.12 83.83 90 top
RE290  0_0402_5%  [R0402_0OHM]  293.26 73.12 270 top
RE292  0_0402_5%  [R_0402]  303.61 96.03 180 top
RE300  130K_0402_5%  [R_0402]  300.61 89.88 270 top
RE301  10K_0402_5%  [R_0402]  293.25 83.46 180 top
RE302  2.2K_0402_5%  [R_0402]  289.84 74.36 0 top
RE303  2.2K_0402_5%  [R_0402]  289.84 73.47 0 top
RE304  0_0402_5%  [R_0402]  308.49 93.54 90 top
RE306  0_0402_5%  [R_0402]  273.23 74.38 0 bottom
RE308  0_0402_5%  [R_0402]  306.66 87.43 270 top
RE312  300_0402_5%  [R_0402]  310.2 68.9 270 top
RE313  10K_0402_5%  [R_0402]  311.11 68.91 270 top
RE314  100_0402_1%  [R_0402]  299.94 67.57 0 top
RE318  0_0402_5%  [R0402_0OHM]  296.6 64.87 0 top
RE324  100K_0402_5%  [R_0402]  292.13 68.73 180 top
RE337  0_0402_5%  [R_0402]  306.22 67.13 90 top
RE338  0_0402_5%  [R_0402]  308.69 77.36 180 top
RE339  0_0402_5%  [R_0402]  308.42 72.76 180 top
RE340  10K_0402_5%  [R_0402]  268.09 75.77 0 bottom
RE341  0_0402_5%  [R_0402]  308.3 69.2 180 top
RE342  10K_0402_5%  [R_0402]  302.18 66.99 0 top
RE343  240K_0402_5%  [R_0402]  298.01 66.3 90 top
RE348  10K_0402_5%  [R_0402]  279.58 76.73 0 top
RE349  43K_0402_1%  [R_0402]  308.43 73.64 180 top
RE350  33_0402_5%  [R_0402]  287.74 78.38 180 top
RE360  0_0402_5%  [R0402_0OHM]  313.62 75.46 0 top
RE361  49.9K_0402_1%  [R_0402]  297.05 66.55 180 top
RE362  100K_0402_5%  [R_0402]  297.05 67.57 180 top
RE363  0_0402_5%  [R_0402]  301.97 68.82 270 top
RE364  0_0402_5%  [R0402_0OHM]  307.51 74.51 0 top
RE365  100K_0402_5%  [R_0402]  297.45 83.77 90 top
RE366  24.9_0402_1%  [R_0402]  313.62 77.23 0 top
RE367  45.3_0402_1%  [R_0402]  317.89 73.12 270 top
RE368  24.9_0402_1%  [R_0402]  314.13 74.06 0 top
RE369  45.3_0402_1%  [R_0402]  311.46 65.55 0 top
RE370  24.9_0402_1%  [R_0402]  313.62 76.35 0 top
RE371  45.3_0402_1%  [R_0402]  311.46 64.66 0 top
RE372  24.9_0402_1%  [R_0402]  307.6 76.34 0 top
RE373  45.3_0402_1%  [R_0402]  317 73.12 270 top
RE374  24.9_0402_1%  [R_0402]  307.73 79.52 0 top
RE375  0_0402_5%  [R_0402]  268.17 66.81 90 bottom
RE376  1K_0402_5%  [R_0402]  310.27 64.66 90 top
RE377  1K_0402_5%  [R_0402]  315.98 73.12 270 top
RE505  100K_0402_5%  [R_0402]  269.49 91.02 90 top
RE507  100K_0402_5%  [R_0402]  290.75 75.33 180 top
RE508  100K_0402_5%  [R_0402]  287.33 68.6 0 top
RE512  100K_0402_5%  [R_0402]  309.5 70.88 0 top
RE513  100K_0402_5%  [R_0402]  304.17 70.01 270 bottom
RE514  0_0402_5%  [R_0402]  286.82 76.6 0 top
RE515  0_0402_5%  [R0402_0OHM]  286.82 77.49 0 top
RE524  2.2K_0402_5%  [R_0402]  310.33 78.07 0 top
RE525  2.2K_0402_5%  [R_0402]  310.33 77.2 0 top
RE526  10K_0402_5%  [R_0402]  299.2 90.06 0 bottom
RE530  1M_0402_5%  [R_0402]  292.7 86.58 90 top
RE532  4.7K_0402_5%  [R_0402]  301.91 90.05 180 bottom
RE536  0_0402_5%  [R_0402]  279.6 77.73 0 top
RE537  10K_0402_5%  [R_0402]  284.87 80.47 180 top
RE539  100_0402_5%  [R_0402]  306.67 91.48 0 top
RI13  10K_0402_5%  [R_0402]  305.69 62.5 180 top
RI14  22.1K_0402_1%  [R_0402]  311.79 61.94 270 top
RI27  0_0402_5%  [R_0402-NPM]  292.49 45.43 270 top
RI28  0_0402_5%  [R_0402-NPM]  291.47 45.43 270 top
RI29  0_0402_5%  [R_0402-NPM]  295.6 47.4 270 top
RI30  0_0402_5%  [R_0402-NPM]  294.71 47.4 270 top
RI34  4.7K_0402_5%  [R_0402]  303.66 61.44 270 top
RI35  0_0402_5%  [R_0402]  296.85 53.61 0 top
RI36  4.99K_0402_1%  [R_0402]  305.06 54.4 90 top
RI37  2K_0402_5%  [R_0402]  306.33 50.68 180 top
RI38  4.7K_0402_5%  [R_0402]  302.65 62.68 90 top
RI39  4.7K_0402_5%  [R_0402]  302.65 60.52 90 top
RI40  4.7K_0402_5%  [R_0402]  300.61 62.68 90 top
RI41  4.7K_0402_5%  [R_0402]  300.61 60.52 90 top
RI42  4.7K_0402_5%  [R_0402]  302.07 52.67 270 top
RI43  4.7K_0402_5%  [R_0402]  302.07 50.45 270 top
RI44  4.7K_0402_5%  [R_0402]  300.23 52.67 270 top
RI45  4.7K_0402_5%  [R_0402]  300.23 50.45 270 top
RI47  0_0402_5%  [R_0402-NPM]  290.45 45.43 270 top
RI48  0_0402_5%  [R_0402-NPM]  289.44 45.43 270 top
RI49  0_0402_5%  [R_0402-NPM]  197.73 24.4 0 bottom
RI50  0_0402_5%  [R_0402-NPM]  197.73 23.39 0 bottom
RI51  4.7K_0402_5%  [R_0402]  299.6 62.68 90 top
RI52  4.7K_0402_5%  [R_0402]  299.6 60.52 90 top
RI53  4.7K_0402_5%  [R_0402]  301.63 62.68 90 top
RI54  4.7K_0402_5%  [R_0402]  301.63 60.52 90 top
RI55  4.7K_0402_5%  [R_0402]  306.67 49.83 270 top
RI56  4.7K_0402_5%  [R_0402]  305.78 49.83 270 top
RI57  4.7K_0402_5%  [R_0402]  301.12 52.67 270 top
RI58  4.7K_0402_5%  [R_0402]  301.12 50.45 270 top
RI79  0_0603_5%  [R_0603]  315.78 68.26 180 top
RI80  0_0603_5%  [R0603_0OHM]  315.78 69.46 180 top
RI81  0_0402_5%  [R0402_0OHM]  304.16 51.95 180 top
RL1  10K_0402_5%  [R_0402]  273.13 84.09 180 top
RL2  10K_0402_5%  [R_0402]  273.13 82.57 180 top
RL3  0_0402_5%  [R0402_0OHM]  283.39 84.98 0 top
RL4  4.7K_0402_5%  [R_0402]  279.38 80.5 270 top
RL5  10K_0402_5%  [R_0402]  280.4 80.49 270 top
RL6  4.7K_0402_5%  [R_0402]  283.09 80.47 270 top
RL7  0_0402_5%  [R0402_0OHM]  282.21 79.57 90 top
RL8  0_0603_5%  [R0603_0OHM]  283.53 81.68 0 top
RL9  10K_0402_5%  [R_0402]  281.31 80.49 270 top
RL11  1M_0402_5%  [R_0402]  285.37 89.35 90 top
RL12  1K_0402_5%  [R_0402]  273.13 85.11 180 top
RL13  3.01K_0402_1%  [R_0402]  283.34 89.35 90 top
RL14  150_0402_5%  [R_0402]  279.21 100.53 90 top
RL15  75_0402_1%  [R_0402]  292.99 101.31 270 top
RL16  75_0402_1%  [R_0402]  295.53 101.31 270 top
RL17  75_0402_1%  [R_0402]  298.84 101.31 270 top
RL18  75_0402_1%  [R_0402]  302.39 101.31 270 top
RL19  150_0402_5%  [R_0402]  280.17 100.53 90 top
RL20  150_0402_5%  [R_0402]  282.38 100.48 0 top
RL29  1M_0402_5%  [R_0402]  281.31 101.44 270 top
RL30  1M_0402_5%  [R_0402]  278.26 101.44 270 top
RL34  0_0402_5%  [R0402_0OHM]  285.32 88.16 180 top
RL70  10K_0402_5%  [R_0402]  142.63 33.68 270 top
RL71  2.2_0603_5%  [R_0603]  283.6 91.78 90 top
RL72  2.2_0603_5%  [R_0603]  282.33 91.78 90 top
RL73  2.2_0603_5%  [R_0603]  281.06 91.78 90 top
RL74  2.2_0603_5%  [R_0603]  279.79 91.78 90 top
RL75  2.2_0603_5%  [R_0603]  278.52 91.78 90 top
RL76  2.2_0603_5%  [R_0603]  277.25 91.78 90 top
RL77  2.2_0603_5%  [R_0603]  275.98 91.78 90 top
RL78  2.2_0603_5%  [R_0603]  274.71 91.78 90 top
RN1  100K_0402_5%  [R_0402]  282.26 40.58 90 bottom
RN2  100K_0402_5%  [R_0402]  277.75 38.04 90 top
RN3  10K_0402_5%  [R_0402]  276.48 36.72 90 bottom
RN4  10K_0402_5%  [R_0402]  276.36 40.14 90 bottom
RN5  10K_0402_5%  [R_0402]  276.36 41.92 90 bottom
RN6  4.7K_0402_5%  [R_0402]  271.96 62.76 0 top
RN7  4.7K_0402_5%  [R_0402]  272.04 62.25 0 bottom
RN8  4.7K_0402_5%  [R_0402]  272.88 63.77 180 top
RN9  4.7K_0402_5%  [R_0402]  272.04 63.14 0 bottom
RN10  4.7K_0402_5%  [R_0402]  280.68 62.38 0 top
RN11  4.7K_0402_5%  [R_0402]  278.14 62.38 0 bottom
RN12  4.7K_0402_5%  [R_0402]  281.56 64.53 180 top
RN13  4.7K_0402_5%  [R_0402]  276.23 63.26 0 bottom
RN14  4.7K_0402_5%  [R_0402]  271.96 64.79 0 top
RN15  7.87K_0402_1%  [R_0402]  272.04 64.03 0 bottom
RN16  4.7K_0402_5%  [R_0402]  281.56 60.98 180 top
RN17  4.7K_0402_5%  [R_0402]  278.14 61.49 0 bottom
RN18  4.7K_0402_5%  [R_0402]  279.41 58.62 90 top
RN19  4.7K_0402_5%  [R_0402]  278.45 59.53 270 top
RN20  4.7K_0402_5%  [R_0402]  281.56 63.65 180 top
RN21  4.7K_0402_5%  [R_0402]  279.02 63.26 180 bottom
RN25  10K_0402_5%  [R_0402]  258.83 42.23 90 top
RN26  10K_0402_5%  [R_0402]  260.86 42.11 90 top
RN27  10K_0402_5%  [R_0402]  268.43 44.47 180 top
RN28  10K_0402_5%  [R_0402]  261.88 42.11 90 top
RN30  4.99K_0402_1%  [R_0402]  263.91 43.02 270 top
RN31  4.99K_0402_1%  [R_0402]  294.25 55.33 0 top
RN37  10K_0402_5%  [R_0402]  294 27.77 0 top
RN38  10K_0402_5%  [R_0402]  259.54 44.47 180 top
RN39  10K_0402_5%  [R_0402]  259.85 43.02 270 top
RN40  10K_0402_5%  [R_0402]  267.52 45.48 0 top
RN41  10K_0402_5%  [R_0402]  262.9 43.02 270 top
RN42  10K_0402_5%  [R_0402]  261.75 51.91 270 top
RN43  10K_0402_5%  [R_0402]  261.75 53.15 90 top
RN44  10K_0402_5%  [R_0402]  265.44 52.04 270 top
RN49  10K_0402_5%  [R_0402]  265.94 42.11 90 top
RN50  10K_0402_5%  [R_0402]  264.55 52.04 270 top
RN51  10K_0402_5%  [R_0402]  268.43 47.52 180 top
RN52  10K_0402_5%  [R_0402]  264.93 43.02 270 top
RN53  10K_0402_5%  [R_0402]  263.66 51.12 90 top
RN54  10K_0402_5%  [R_0402]  267.52 46.5 0 top
RN55  10K_0402_5%  [R_0402]  292.61 52.29 270 bottom
RN56  10K_0402_5%  [R_0402]  295.15 52.34 180 top
RN57  10K_0402_5%  [R_0402]  292.99 59.58 180 bottom
RN58  10K_0402_5%  [R_0402]  295.17 53.29 180 top
RN59  10K_0402_5%  [R_0402]  291.67 51.38 90 bottom
RN60  10K_0402_5%  [R_0402]  294.26 51.45 0 top
RN61  10K_0402_5%  [R_0402]  292.11 60.6 0 bottom
RN62  10K_0402_5%  [R_0402]  294.25 54.31 0 top
RN63  10K_0402_5%  [R_0402]  226.14 35.83 180 top
RN64  10K_0402_5%  [R_0402]  219.64 32.28 0 top
RN65  10K_0402_5%  [R_0402]  209.68 32.39 90 top
RN69  10K_0402_5%  [R_0402]  295.17 57.23 180 top
RN70  10K_0402_5%  [R_0402]  288.27 56.15 180 bottom
RN71  10K_0402_5%  [R_0402]  290.96 57.93 180 bottom
RN72  10K_0402_5%  [R_0402]  294.25 56.28 0 top
RN73  10K_0402_5%  [R_0402]  287.36 55.26 0 bottom
RN74  10K_0402_5%  [R_0402]  289.18 57.93 180 bottom
RN77  0_0402_5%  [R0402_0OHM]  286.28 39.13 180 bottom
RN78  0_0402_5%  [R0402_0OHM]  286.28 38.25 180 bottom
RN81  0_0402_5%  [R0402_0OHM]  283.67 42.44 180 bottom
RN82  0_0402_5%  [R0402_0OHM]  283.67 43.33 180 bottom
RN99  0_0402_5%  [R0402_0OHM]  292.22 27.77 0 top
RN100  0_0402_5%  [R_0402]  267.47 25.51 180 bottom
RN101  0_0402_5%  [R_0402]  264.8 25.51 0 bottom
RN171  100K_0402_5%  [R_0402]  212.67 34.93 90 top
RN174  10K_0402_5%  [R_0402]  266.32 51.12 90 top
RN176  10K_0402_5%  [R_0402]  262.64 54.07 270 top
RN179  10K_0402_5%  [R_0402]  262.64 51 90 top
RN182  0_0402_5%  [R_0402]  209.29 36.85 0 top
RN183  100K_0402_5%  [R_0402]  211.71 34 270 top
RN184  0_0402_5%  [R_0402]  226.14 33.8 180 top
RN185  100K_0402_5%  [R_0402]  225.23 32.78 0 top
RN186  0_0402_5%  [R_0402]  226.14 31.77 180 top
RN187  0_0402_5%  [R_0402]  219.64 35.32 0 top
RN188  100K_0402_5%  [R_0402]  220.55 36.34 180 top
RN189  0_0402_5%  [R_0402]  219.64 34.31 0 top
RN192  0_0402_5%  [R_0402]  211.71 35.84 270 top
RN223  0_0402_5%  [R_0402]  208.73 33.3 270 top
RN224  0_0402_5%  [R_0402]  220.55 33.29 180 top
RN225  0_0402_5%  [R_0402]  225.23 34.82 0 top
RPC1  33_0804_8P4R_5%  [RP_0804_8P4R]  154.67 60.38 90 bottom
RPC3  10K_8P4R_5%  [RP_0804_8P4R]  136.28 79.27 270 bottom
RPC4  10K_8P4R_5%  [RP_0804_8P4R]  145.99 70.32 0 bottom
RPE7  10K_8P4R_5%  [RP_0804_8P4R]  274.27 82.24 180 bottom
RPE9  100K_0804_8P4R_5%  [RP_0804_8P4R]  310.18 81.02 0 top
RPE10  100K_0804_8P4R_5%  [RP_0804_8P4R]  306.98 88.85 90 top
RPE11  100K_0804_8P4R_5%  [RP_0804_8P4R]  305.68 65.79 270 top
RPE12  2.2K_0804_8P4R_5%  [RP_0804_8P4R]  312.84 79.88 90 top
RR3  10K_0402_5%  [R_0402]  26.73 45.23 90 top
RR4  6.2K_0402_1%  [R_0402]  29.47 53.85 90 top
RR5  0_0402_5%  [R0402_0OHM]  21.66 52.77 90 top
RR6  0_0402_5%  [R0402_0OHM]  21.67 50.82 180 top
RR7  0_0402_5%  [R0402_0OHM]  21.67 49.8 180 top
RR8  0_0402_5%  [R0402_0OHM]  21.67 48.79 180 top
RR9  0_0402_5%  [R0402_0OHM]  23.82 53.41 90 top
RR10  0_0402_5%  [R0402_0OHM]  22.93 53.41 90 top
RR19  10K_0402_5%  [R_0402]  27.74 46.14 270 top
RT50  3.3K_0402_5%  [R_0402]  33.41 89.73 90 bottom
RT51  3.3K_0402_5%  [R_0402]  32.39 89.73 90 bottom
RT52  3.3K_0402_5%  [R_0402]  31.37 89.73 90 bottom
RT53  3.3K_0402_5%  [R_0402]  30.1 89.73 90 bottom
RT54  0_0402_5%  [R0402_0OHM]  32.9 94.05 90 top
RT55  0_0402_5%  [R0402_0OHM]  31.88 94.05 90 top
RT56  0_0402_5%  [R0402_0OHM]  30.87 94.05 90 top
RT57  0_0402_5%  [R0402_0OHM]  29.85 94.05 90 top
RT58  0_0402_5%  [R0402_0OHM]  38.04 81.48 90 bottom
RT59  0_0402_5%  [R0402_0OHM]  39.38 82.39 270 bottom
RT60  0_0402_5%  [R0402_0OHM]  38.31 79.01 180 top
RT63  0_0402_5%  [R0402_0OHM]  33.53 86.43 90 top
RT64  0_0402_5%  [R_0402]  37.39 78.12 0 top
RT65  0_0402_5%  [R_0402]  37.39 77.23 0 top
RT66  3.3K_0402_5%  [R_0402]  23.68 84.73 0 top
RT67  3.3K_0402_5%  [R_0402]  36.77 82.17 90 bottom
RT68  10K_0402_5%  [R_0402]  37.39 79.9 0 top
RT69  0_0402_5%  [R0402_0OHM]  36.62 85.29 90 top
RT70  0_0402_5%  [R0402_0OHM]  37.33 87.27 0 top
RT71  1M_0402_5%  [R_0402]  33.08 79.75 180 bottom
RT72  0_0402_5%  [R0402_0OHM]  31.82 75.79 270 top
RT73  0_0402_5%  [R0402_0OHM]  35.5 76.04 270 top
RT74  0_0402_5%  [R_0402]  33.84 78.31 0 bottom
RT75  0_0402_5%  [R_0402]  30.93 76.04 270 top
RT76  10K_0402_1%  [R_0402]  28.58 80.54 180 bottom
RT81  100K_0402_5%  [R_0402]  33.58 85.74 0 bottom
RT82  1M_0402_5%  [R_0402]  32.72 85.74 180 bottom
RT83  0_0402_5%  [R0402_0OHM]  33.61 84.85 180 bottom
RT84  0_0402_5%  [R_0402]  31.56 82.65 90 bottom
RT85  0_0402_5%  [R_0402]  30.62 82.65 90 bottom
RT86  1M_0402_5%  [R_0402]  34.61 75.79 270 top
RT87  0_0402_5%  [R_0402]  25.9 81.04 0 top
RT88  0_0402_5%  [R_0402]  25.9 81.93 0 top
RT89  0_0402_5%  [R0402_0OHM]  25.9 82.82 0 top
RT90  0_0402_5%  [R0402_0OHM]  23.68 82.89 0 top
RT92  0_0402_5%  [R0402_0OHM]  25.9 83.84 0 top
RT93  0_0402_5%  [R0402_0OHM]  23.68 83.77 0 top
RT95  100K_0402_5%  [R_0402]  28.28 86 180 top
RT96  100K_0402_5%  [R_0402]  29.14 86 0 top
RT97  0_0402_5%  [R_0402]  37.46 85.49 0 top
RT98  0_0402_5%  [R_0402]  32.71 75.79 270 top
RT99  0_0402_5%  [R0402_0OHM]  33.72 75.79 270 top
RT100  15K_0402_1%  [R_0402]  31.62 85.11 0 top
RT101  100K_0402_5%  [R_0402]  33.07 80.64 180 bottom
RT103  0_0402_5%  [R_0402]  30.04 76.04 270 top
RT104  0_0402_5%  [R0402_0OHM]  27.64 77.3 180 top
RT105  0_0402_5%  [R0402_0OHM]  29.15 76.04 270 top
RT106  10K_0402_5%  [R_0402]  33.36 82.85 180 bottom
RT107  10K_0402_5%  [R_0402]  34.69 81.72 90 bottom
RT108  0_0402_5%  [R0402_0OHM]  27.64 78.69 180 top
RT109  0_0402_5%  [R0402_0OHM]  27.64 79.58 180 top
RT110  0_0402_5%  [R_0402]  33.55 76.79 180 bottom
RT111  100K_0402_5%  [R_0402]  38.49 99.89 90 bottom
RT120  0_0402_5%  [R0402_0OHM]  13.55 96.97 180 bottom
RT121  0_0402_5%  [R0402_0OHM]  13.55 97.99 180 bottom
RT122  0_0402_5%  [R0402_0OHM]  13.03 91.2 0 top
RT123  0_0402_5%  [R0402_0OHM]  13.03 92.21 0 top
RT130  100K_0402_5%  [R_0402]  22.36 89.76 270 top
RT131  100K_0402_5%  [R_0402]  21.47 89.76 270 top
RT132  0_0402_5%  [R_0402]  19.63 89.76 270 bottom
RT133  0_0402_5%  [R_0402]  20.52 89.76 270 bottom
RT135  1K_0402_5%  [R_0402]  22.48 99.57 90 top
RT136  1K_0402_5%  [R_0402]  20.45 99.57 90 top
RT137  1K_0402_5%  [R_0402]  25.33 96.54 0 top
RT138  1K_0402_5%  [R_0402]  25.33 98.57 0 top
RT139  1K_0402_5%  [R_0402]  25.33 95.52 0 top
RT140  1K_0402_5%  [R_0402]  25.33 94.51 0 top
RT141  1K_0402_5%  [R_0402]  16.59 92.59 180 top
RT142  1K_0402_5%  [R_0402]  16.59 93.49 180 top
RT143  1K_0402_5%  [R_0402]  16.6 96.04 180 top
RT144  1K_0402_5%  [R_0402]  16.59 97.99 180 top
RT145  1K_0402_5%  [R_0402]  25.33 92.47 0 top
RT246  0_0402_5%  [R0402_0OHM]  16.39 100.81 270 bottom
RT247  1K_0402_5%  [R_0402]  18.42 99.89 90 bottom
RT248  1K_0402_5%  [R_0402]  20.45 99.89 90 bottom
RT300  1K_0402_5%  [R_0402]  25.33 91.46 0 top
RT301  20K_0402_5%  [R_0402]  25.33 90.44 0 top
RT302  20K_0402_5%  [R_0402]  25.33 97.55 0 top
RT303  20K_0402_5%  [R_0402]  19.44 99.89 90 bottom
RT304  20K_0402_5%  [R_0402]  16.59 96.97 180 top
RT305  20K_0402_5%  [R_0402]  21.4 99.57 90 top
RT306  20K_0402_5%  [R_0402]  25.33 93.49 0 top
RT307  20K_0402_5%  [R_0402]  16.59 94.51 180 top
RT308  4.7K_0402_5%  [R_0402]  17.15 92.68 270 bottom
RT339  0_0402_5%  [R_0402]  37.39 79.01 0 bottom
RT375  0_0402_5%  [R_0402]  24.2 89.88 270 top
RT376  0_0402_5%  [R_0402]  22.8 82.87 90 top
RT377  43K_0402_1%  [R_0402]  30.36 80.4 90 bottom
RT378  10K_0402_5%  [R_0402]  34.47 87.33 0 top
RT379  10K_0402_5%  [R_0402]  34.78 85.41 90 top
RT380  0_0402_5%  [R0402_0OHM]  17.53 92.59 90 top
RT393  100K_0402_5%  [R_0402]  37.39 100.25 180 bottom
RT397  0_0603_5%  [R_0603]  17.07 89.46 90 bottom
RT398  0_0603_5%  [R0603_0OHM]  27.11 100.88 180 bottom
RV1  4.7K_0402_5%  [R_0402]  105.92 87.98 90 bottom
RV2  4.7K_0402_5%  [R_0402]  104.91 87.9 90 bottom
RV3  100K_0402_5%  [R_0402]  92.89 82.5 0 bottom
RV4  270K_0402_5%  [R_0402]  105.54 81.79 90 bottom
RV5  47K_0402_5%  [R_0402]  103.51 81.79 90 bottom
RV6  47K_0402_5%  [R_0402]  122.94 84.35 90 bottom
RV7  100K_0402_5%  [R_0402]  103.64 88.03 90 bottom
RV8  10K_0402_5%  [R_0402]  99.32 88.79 270 bottom
RV10  470_0402_1%  [R_0402]  98.13 103.08 180 top
RV11  470_0402_1%  [R_0402]  98.99 103.08 0 top
RV12  470_0402_1%  [R_0402]  101.68 103.08 180 top
RV13  470_0402_1%  [R_0402]  102.54 103.08 0 top
RV14  470_0402_1%  [R_0402]  108.29 102.06 180 top
RV15  470_0402_1%  [R_0402]  109.15 102.06 0 top
RV16  470_0402_1%  [R_0402]  105.24 103.08 180 top
RV17  470_0402_1%  [R_0402]  106.35 103.08 0 top
RV18  10K_0402_5%  [R_0402]  110.37 100.23 90 top
RV19  10K_0402_5%  [R_0402]  116.65 106.9 270 top
RV20  1M_0402_5%  [R_0402]  115.37 111.65 0 top
RV21  20K_0402_5%  [R_0402]  114.25 108.71 90 top
RV22  2.2K_0402_5%  [R_0402]  113.11 112.27 0 bottom
RV23  2.2K_0402_5%  [R_0402]  116.02 109.89 270 bottom
RV24  5.6_0402_5%  [R_0402]  98.18 104.4 90 top
RV25  5.6_0402_5%  [R_0402]  99.19 104.4 90 top
RV26  200_0402_5%  [R_0402]  99.14 106.44 180 top
RV27  5.6_0402_5%  [R_0402]  101.73 104.4 90 top
RV28  5.6_0402_5%  [R_0402]  102.75 104.4 90 top
RV29  200_0402_5%  [R_0402]  102.7 106.42 180 top
RV30  5.6_0402_5%  [R_0402]  108.08 104.4 90 top
RV31  5.6_0402_5%  [R_0402]  109.1 104.4 90 top
RV32  200_0402_5%  [R_0402]  109.1 106.39 180 top
RV33  5.6_0402_5%  [R_0402]  105.29 104.4 90 top
RV34  5.6_0402_5%  [R_0402]  106.3 104.4 90 top
RV35  200_0402_5%  [R_0402]  106.25 106.39 180 top
RV70  100K_0402_5%  [R_0402]  94.82 95.71 180 top
RV71  100K_0402_5%  [R_0402]  94.82 97.74 180 top
RV72  100K_0402_5%  [R_0402]  94.82 99.9 180 top
RV73  1M_0402_5%  [R_0402]  99.7 101.87 90 bottom
RV74  1M_0402_5%  [R_0402]  104.02 101.87 0 bottom
RV75  1M_0402_5%  [R_0402]  108.64 93.42 0 top
RV76  100K_0402_5%  [R_0402]  94.82 94.57 180 top
RV77  100K_0402_5%  [R_0402]  94.82 96.6 180 top
RV78  100K_0402_5%  [R_0402]  94.82 98.76 180 top
RV79  4.7K_0402_5%  [R_0402]  101.48 101.87 90 bottom
RV80  4.7K_0402_5%  [R_0402]  100.59 101.87 90 bottom
RV81  4.7K_0402_5%  [R_0402]  108.84 86.52 270 top
RV82  4.7K_0402_5%  [R_0402]  109.35 87.9 90 top
RV83  4.7K_0402_5%  [R_0402]  107.83 86.52 270 top
RV84  4.7K_0402_5%  [R_0402]  107.83 87.89 90 top
RV85  4.7K_0402_5%  [R_0402]  106.81 86.52 270 top
RV86  4.7K_0402_5%  [R_0402]  106.81 88.8 270 top
RV87  4.7K_0402_5%  [R_0402]  105.8 86.52 270 top
RV88  4.7K_0402_5%  [R_0402]  104.53 86.52 270 top
RV89  4.7K_0402_5%  [R_0402]  98.94 88.79 270 top
RV90  4.7K_0402_5%  [R_0402]  97.92 89.06 270 top
RV91  4.7K_0402_5%  [R_0402]  95.89 88.79 270 top
RV92  4.7K_0402_5%  [R_0402]  96.97 89.06 270 top
RV93  4.7K_0402_5%  [R_0402]  94.87 88.79 270 top
RV94  4.7K_0402_5%  [R_0402]  93.86 88.79 270 top
RV95  4.7K_0402_5%  [R_0402]  92.97 88.79 270 top
RV96  4.7K_0402_5%  [R_0402]  91.95 88.79 270 top
RV97  4.99K_0402_1%  [R_0402]  99.95 88.8 270 top
RV102  100K_0402_5%  [R_0402]  274.52 59.82 90 bottom
RV106  4.7K_0402_5%  [R_0402]  275.4 59.82 90 bottom
RV107  4.7K_0402_5%  [R_0402]  276.67 59.82 90 bottom
RV116  75_0402_1%  [R_0402]  318.39 90.43 90 bottom
RV117  75_0402_1%  [R_0402]  316.11 90.43 90 bottom
RV118  75_0402_1%  [R_0402]  312.68 75.09 270 bottom
RV119  2.2K_0402_5%  [R_0402]  317.63 80.93 270 top
RV120  2.2K_0402_5%  [R_0402]  317.89 74.44 180 top
RV121  1K_0402_5%  [R_0402]  315.6 76.36 270 top
RV122  1K_0402_5%  [R_0402]  315.6 78.64 270 top
RV123  4.7K_0402_5%  [R_0402]  278.15 51.26 180 top
RV124  4.7K_0402_5%  [R_0402]  275.2 51.26 0 top
RZ8  2.2K_0402_5%  [R_0402]  217.86 10.43 0 top
RZ9  2.2K_0402_5%  [R_0402]  217.86 11.7 0 top
RZ10  100K_0402_5%  [R_0402]  220.15 20.59 0 top
RZ18  4.7K_0402_5%  [R_0402]  215.35 19.42 90 top
RZ19  4.7K_0402_5%  [R_0402]  215.35 22.12 270 top
RZ20  2.2K_0402_5%  [R_0402]  220.86 24.15 180 top
RZ21  2.2K_0402_5%  [R_0402]  220.86 25.29 180 top
RZ22  0_0402_5%  [R_0402]  216.24 20.34 270 top
RZ23  0_0402_5%  [R_0402]  216.24 21.2 90 top
RZ25  150_0402_5%  [R_0402]  269.12 75.71 180 top
RZ26  0_0402_5%  [R0402_0OHM]  216.74 24.15 180 top
RZ28  330_0402_5%  [R_0402]  284.61 53.61 270 top
RZ29  0_0402_5%  [R0402_0OHM]  216.74 25.16 180 top
RZ32  330_0402_5%  [R_0402]  316.92 98.57 0 bottom
RZ38  100K_0402_5%  [R_0402]  189.06 14.81 180 top
RZ40  100K_0402_5%  [R_0402]  272.29 50.97 0 bottom
RZ43  47K_0402_5%  [R_0402]  290.45 50.51 270 top
RZ56  0_0402_5%  [R0402_0OHM]  197.24 13.35 0 top
RZ58  33_0402_5%  [R_0402]  161.6 34.69 0 top
RZ59  33_0402_5%  [R_0402]  160.14 36.47 0 top
RZ60  33_0402_5%  [R_0402]  161.92 38.88 0 top
RZ61  0_0402_5%  [R0402_0OHM]  157.6 37.99 0 top
RZ62  10K_0402_5%  [R_0402]  165.75 33.36 180 top
RZ63  33_0402_5%  [R_0402]  161.92 37.99 0 top
RZ64  0_0402_5%  [R0402_0OHM]  199.14 7.77 0 top
RZ65  0_0402_5%  [R_0402]  199.14 8.65 0 top
RZ69  10K_0402_5%  [R_0402]  162.82 40.67 270 top
RZ70  0_0402_5%  [R0402_0OHM]  188.14 15.77 0 top
RZ71  0_0402_5%  [R_0402]  188.14 16.66 0 top
RZ76  0_0402_5%  [R_0402]  296.55 48.84 90 top
RZ77  0_0402_5%  [R_0402]  297.44 48.84 90 top
RZ78  0_0402_5%  [R_0402]  197.29 12.34 0 top
RZ79  0_0402_5%  [R_0402]  197.29 11.32 0 top
RZ80  0_0402_5%  [R_0402]  197.29 10.31 0 top
RZ81  0_0402_5%  [R_0402]  197.29 9.29 0 top
RZ85  0_0402_5%  [R0402_0OHM]  219.64 7.13 0 top
RZ87  0_0402_5%  [R0402_0OHM]  220.15 21.48 0 top
RZ89  0_0402_5%  [R0402_0OHM]  172.47 40.35 270 top
RZ111  10K_0402_5%  [R_0402]  171.63 37.93 0 top
RZ112  0_0402_5%  [R_0402]  167.84 32.45 90 top
RZ113  100_0402_5%  [R_0402]  168.18 44.34 0 top
RZ114  0_0402_5%  [R_0402]  220.15 19.58 0 top
RZ116  10K_0402_5%  [R_0402]  219.08 24.02 180 top
RZ117  10K_0402_5%  [R_0402]  219.08 25.29 180 top
RZ119  0_0402_5%  [R_0402]  123.32 27.63 90 top
RZ120  0_0402_5%  [R0402_0OHM]  129.88 29.92 180 top
RZ128  0_0201_5%  [R_0201]  301.57 46.73 270 top
RZ129  0_0201_5%  [R_0201]  302.2 46.79 270 top
RZ130  0_0201_5%  [R_0201]  302.84 46.79 270 top
RZ131  0_0402_5%  [R_0402]  298.46 50.2 270 top
RZ132  0_0402_5%  [R_0402]  299.34 50.2 270 top
RZ151  0_0603_5%  [R_0603]  143.64 89.93 0 bottom
RZ154  10K_0402_5%  [R_0402]  282.88 61.3 0 top
RZ155  10K_0402_5%  [R_0402]  283.8 62.25 180 top
RZ156  10K_0402_5%  [R_0402]  286.1 59.67 90 bottom
RZ157  10K_0402_5%  [R_0402]  285.15 60.59 270 bottom
RZ158  10K_0402_5%  [R_0402]  293.2 62.76 180 bottom
RZ159  10K_0402_5%  [R_0402]  292.28 61.8 0 bottom
RZ160  10K_0402_5%  [R_0402]  287.03 59.67 90 bottom
RZ161  10K_0402_5%  [R_0402]  287.91 60.59 270 bottom
RZ162  10K_0402_5%  [R_0402]  290.61 59.67 90 bottom
RZ163  10K_0402_5%  [R_0402]  289.72 60.59 270 bottom
RZ164  10K_0402_5%  [R_0402]  289.81 68.46 270 bottom
RZ165  10K_0402_5%  [R_0402]  288.86 67.54 90 bottom
RZ166  10K_0402_5%  [R_0402]  293.2 63.65 180 bottom
RZ167  10K_0402_5%  [R_0402]  292.28 64.66 0 bottom
RZ320  0_0402_5%  [R_0402]  132.59 79.52 180 bottom
RZ326  0_0402_5%  [R_0402]  292.17 42.19 270 top
RZ334  51_0402_5%  [R_0402]  117.8 108.84 90 bottom
RZ335  15K_0402_5%  [R_0402]  117.8 111.54 270 bottom
RZ345  0_0402_5%  [R0402_0OHM]  268.79 53.36 0 top
RZ346  0_0402_5%  [R0402_0OHM]  214.91 24.1 270 top
RZ347  0_0402_5%  [R0402_0OHM]  214.91 24.96 90 top
RZ348  4.99K_0402_1%  [R_0402]  288.83 60.59 270 bottom
RZ354  10K_0402_5%  [R_0402]  286.03 68.46 270 bottom
RZ355  10K_0402_5%  [R_0402]  285.15 67.54 90 bottom
RZ356  10K_0402_5%  [R_0402]  286.95 68.46 270 bottom
RZ357  10K_0402_5%  [R_0402]  287.91 67.54 90 bottom
RZ358  10K_0402_5%  [R_0402]  290.76 68.46 270 bottom
RZ359  10K_0402_5%  [R_0402]  291.72 67.54 90 bottom
RZ360  100K_0402_5%  [R_0402]  291.28 65.79 90 top
RZ361  150_0402_5%  [R_0402]  267.72 68.98 90 top
RZ362  10K_0402_5%  [R_0402]  166.95 32.45 90 top
RZ363  0_0402_5%  [R0402_0OHM]  172.55 37.04 180 top
SW1  SS3-CMFTQR9_3P  [SW_SS3-CMFTQR9_3P]  273.53 88.39 90 bottom
SW3  SKRBAAE010_4P  [SW_SKRBAAE010_4P]  322.19 92.65 90 top
T1  PAD~D  [TPC12]  111.29 65.29 0 top
T2  PAD~D  [TPC12]  110.01 65.19 0 top
T3  PAD~D  [TPC12]  104.04 42.63 180 bottom
T4  PAD~D  [TPC12]  103.02 41.58 180 bottom
T5  PAD~D  [TPC12]  105.42 53.17 0 top
T6  PAD~D  [TPC12]  107.65 54.09 0 top
T9  PAD~D  [TPC12]  90.3 82.57 180 bottom
T10  PAD~D  [TPC12]  107.52 76.09 180 bottom
T11  PAD~D  [TPC12]  106.62 74.63 180 bottom
T12  PAD~D  [TPC12]  94.87 41.94 180 bottom
T13  PAD~D  [TPC12]  93.06 43.12 180 bottom
T14  PAD~D  [TPC12]  128.62 55 0 top
T15  PAD~D  [TPC12]  130.12 54.62 0 top
T16  PAD~D  [TPC12]  92.08 41.8 180 bottom
T17  PAD~D  [TPC12]  94.34 43.11 180 bottom
T18  PAD~D  [TPC12]  134.03 56.14 0 top
T19  PAD~D  [TPC12]  138.94 79.2 180 bottom
T50  PAD~D  [TPC12]  81.16 2.66 0 top
T51  PAD~D  [TPC12]  82.43 15.19 0 top
T54  PAD~D  [TPC12]  167.02 4.44 0 top
T55  PAD~D  [TPC12]  163.71 14.43 0 top
T87  PAD~D  [TPC12]  318.18 83.66 180 bottom
T88  PAD~D  [TPC12]  274.02 84.63 90 top
T89  PAD~D  [TPC12]  273.99 83.33 90 top
T113  PAD~D  [TPC12]  91.79 43.07 180 bottom
T114  PAD~D  [TPC12]  93.57 41.93 180 bottom
T115  PAD~D  [TPC12]  130.84 49.4 0 top
T120  PAD~D  [TPC12]  130.18 62.72 0 top
T122  PAD~D  [TPC12]  120.08 64.36 0 top
T123  PAD~D  [TPC12]  118.89 54.91 0 top
T126  PAD~D  [TPC12]  142.98 45.46 180 bottom
T127  PAD~D  [TPC12]  143.62 44.32 180 bottom
T128  PAD~D  [TPC12]  142.31 50.88 180 bottom
T129  PAD~D  [TPC12]  143.08 52.06 180 bottom
T130  PAD~D  [TPC12]  142.93 43.22 180 bottom
T132  PAD~D  [TPC12]  98.26 45.42 0 top
T204  PAD~D  [TPC12]  99.7 90.04 0 top
